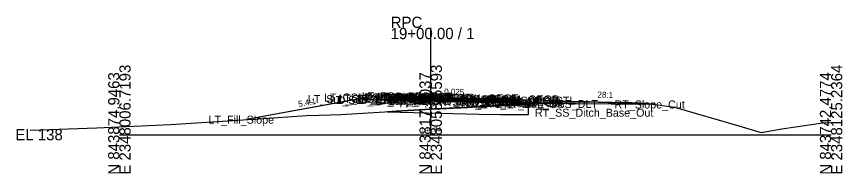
# Model space of a CAD drawing. Extents: x -26 to 203, y -10 to 7538.
# Drawn here: x -3.4 to 202.8, y 5490.3 to 5529.5 of the extents above; entities that cross this region are included whole.
import ezdxf

# ---------------------------------------------------------------- set-up
doc = ezdxf.new("R2010")
doc.units = 0
for name, color, linetype in [('Default', 7, 'Continuous'), ('Exist Cross Section Cell', 7, 'Continuous'), ('Exist XS Center Line Elevation Label', 7, 'Continuous'), ('Exist XS Ground Line', 7, 'Continuous'), ('Prop CMT Pvmt Course 1', 7, 'Continuous'), ('Prop CMT Pvmt Course 2', 7, 'Continuous'), ('Prop CMT Pvmt Course 3', 7, 'Continuous'), ('Prop CMT Pvmt Surface', 7, 'Continuous'), ('Prop CMT Pvmt Surface Shoulder', 7, 'Continuous'), ('Prop CMT Shld Paved Course 1', 7, 'Continuous'), ('Prop CMT Shld Paved Course 2', 7, 'Continuous'), ('Prop CMT Shld Paved Course 3', 7, 'Continuous'), ('Prop CMT Slope Grass', 7, 'Continuous'), ('Prop CMT Subgrade Earthwork', 7, 'Continuous'), ('Prop Road Sect_ Recs - UC (Outline)', 7, 'Continuous'), ('Prop XS Earthwork Shape', 7, 'Continuous'), ('Prop XS SE Text', 7, 'Continuous'), ('Prop XS Side Slope Text', 7, 'Continuous'), ('Scratch_Level_0', 7, 'Continuous')]:
    doc.layers.add(name, color=color, linetype=linetype)

msp = doc.modelspace()

# ---------------------------------------------------------------- linework, layer by layer
at = {"layer": 'Exist Cross Section Cell'}
for p, q in [((100, 5500), (100, 5526.67)), ((22.25, 5500), (100, 5500)), ((100, 5500), (200, 5500))]:
    msp.add_line(p, q, dxfattribs=at)
at = {"layer": 'Exist XS Ground Line'}
msp.add_lwpolyline([(0, 5501.14), (16.64, 5501.73), (35.03, 5502.56), (55.71, 5503.86), (56.28, 5503.9), (57.1, 5503.98), (68.96, 5504.78), (72.1, 5504.89), (77.52, 5505.06), (87.1, 5505.59), (95.79, 5506.1), (100, 5506.34), (102.1, 5506.47), (109.21, 5506.82), (112.93, 5507), (116.65, 5507.23), (123.89, 5507.66), (130.27, 5508.04), (130.72, 5508.03), (131.92, 5508.13), (132.56, 5508.16), (133.8, 5508.19), (135.3, 5508.19), (135.85, 5508.19), (136.47, 5508.19), (138.69, 5508.19), (140.23, 5508.18), (141.17, 5508.17), (142.02, 5508.16), (143.98, 5508.13), (145.36, 5508.11), (147.7, 5508.07), (148.2, 5508.05), (148.66, 5508.05), (150.21, 5508.02), (151.64, 5507.98), (152.22, 5507.94), (153.93, 5507.88), (155.47, 5507.66), (160.91, 5506.9), (176.94, 5502.25), (182.5, 5500.56), (187.68, 5501.44), (197.92, 5503), (200, 5503.05)], dxfattribs=at)
at = {"layer": 'Prop CMT Pvmt Course 1'}
for p, q in [((100, 5509.36), (96, 5509.46)), ((96, 5509.46), (96, 5509.21)), ((96, 5509.21), (100, 5509.11)), ((100, 5509.11), (100, 5509.36)), ((100, 5509.36), (112, 5509.06)), ((100, 5509.11), (100, 5509.36)), ((100, 5509.11), (100, 5509.23)), ((100, 5509.23), (100, 5509.23)), ((100, 5509.23), (100, 5509.11)), ((100, 5509.11), (100, 5509.23)), ((100, 5509.23), (100, 5509.23)), ((100, 5509.23), (100, 5509.11)), ((100, 5509.11), (100, 5509.11)), ((112, 5508.81), (100, 5509.11)), ((100, 5509.11), (100, 5509.11)), ((112, 5509.06), (112, 5508.81))]:
    msp.add_line(p, q, dxfattribs=at)
at = {"layer": 'Prop CMT Pvmt Course 2'}
for p, q in [((100, 5509.11), (96, 5509.21)), ((96, 5509.21), (96, 5508.87)), ((96, 5508.87), (100, 5508.77)), ((100, 5508.77), (100, 5509.11)), ((100, 5508.77), (100, 5509.11)), ((100, 5509.11), (112, 5508.81)), ((112, 5508.47), (100, 5508.77)), ((112, 5508.81), (112, 5508.47))]:
    msp.add_line(p, q, dxfattribs=at)
at = {"layer": 'Prop CMT Pvmt Course 3'}
for p, q in [((100, 5508.77), (96, 5508.87)), ((96, 5508.87), (96, 5508.54)), ((96, 5508.54), (100, 5508.44)), ((100, 5508.44), (100, 5508.77)), ((100, 5508.77), (112, 5508.47)), ((100, 5508.44), (100, 5508.77)), ((112, 5508.14), (100, 5508.44)), ((112, 5508.47), (112, 5508.14))]:
    msp.add_line(p, q, dxfattribs=at)
at = {"layer": 'Prop CMT Pvmt Surface'}
for q in [(96, 5509.46), (112, 5509.06)]:
    msp.add_line((100, 5509.36), q, dxfattribs=at)
at = {"layer": 'Prop CMT Pvmt Surface Shoulder'}
for p, q in [((96, 5509.46), (92, 5509.56)), ((112, 5509.06), (122, 5508.81))]:
    msp.add_line(p, q, dxfattribs=at)
at = {"layer": 'Prop CMT Shld Paved Course 1'}
for p, q in [((92, 5509.56), (91.76, 5509.31)), ((91.76, 5509.31), (96, 5509.21)), ((96, 5509.46), (92, 5509.56)), ((96, 5509.21), (96, 5509.46)), ((112, 5509.06), (122, 5508.81)), ((112, 5508.81), (112, 5509.06)), ((122.26, 5508.55), (112, 5508.81)), ((122, 5508.81), (122.26, 5508.55))]:
    msp.add_line(p, q, dxfattribs=at)
at = {"layer": 'Prop CMT Shld Paved Course 2'}
for p, q in [((91.76, 5509.31), (91.43, 5508.99)), ((91.43, 5508.99), (96, 5508.87)), ((96, 5509.21), (91.76, 5509.31)), ((96, 5508.87), (96, 5509.21)), ((112, 5508.81), (122.26, 5508.55)), ((112, 5508.47), (112, 5508.81)), ((122.6, 5508.21), (112, 5508.47)), ((122.26, 5508.55), (122.6, 5508.21))]:
    msp.add_line(p, q, dxfattribs=at)
at = {"layer": 'Prop CMT Shld Paved Course 3'}
for p, q in [((90.93, 5509), (90.61, 5508.67)), ((90.61, 5508.67), (96, 5508.54)), ((91.43, 5508.99), (90.93, 5509)), ((96, 5508.87), (91.43, 5508.99)), ((96, 5508.54), (96, 5508.87)), ((112, 5508.47), (122.6, 5508.21)), ((112, 5508.14), (112, 5508.47)), ((123.44, 5507.85), (112, 5508.14)), ((122.6, 5508.21), (123.1, 5508.19)), ((123.1, 5508.19), (123.44, 5507.85))]:
    msp.add_line(p, q, dxfattribs=at)
at = {"layer": 'Prop CMT Slope Grass'}
for p, q in [((84, 5509.28), (54, 5503.76)), ((84, 5509.28), (54, 5503.76)), ((92, 5509.56), (84, 5509.28)), ((92, 5509.56), (84, 5509.28)), ((122, 5508.81), (126, 5508.67)), ((126, 5508.67), (155.93, 5507.6))]:
    msp.add_line(p, q, dxfattribs=at)
at = {"layer": 'Prop CMT Subgrade Earthwork'}
for p, q in [((90.61, 5508.67), (81.91, 5508.89)), ((96, 5508.54), (90.61, 5508.67)), ((100, 5508.44), (96, 5508.54)), ((100, 5508.44), (112, 5508.14)), ((112, 5508.14), (123.44, 5507.85)), ((123.44, 5507.85), (155.93, 5507.6))]:
    msp.add_line(p, q, dxfattribs=at)
at = {"layer": 'Prop Road Sect_ Recs - UC (Outline)'}
msp.add_lwpolyline([(117.44, 5505), (124.44, 5505.01), (124.45, 5507.69), (100, 5506.34), (91.45, 5505.84), (89.19, 5505.71), (112, 5505.14)], close=True, dxfattribs=at)
at = {"layer": 'Prop XS Earthwork Shape'}
for points in [[(68.96, 5504.78), (72.1, 5504.89), (77.52, 5505.06), (87.1, 5505.59), (95.79, 5506.1), (100, 5506.34), (102.1, 5506.47), (109.21, 5506.82), (112.93, 5507), (116.65, 5507.23), (123.89, 5507.66), (126.69, 5507.83), (123.44, 5507.85), (112, 5508.14), (100, 5508.44), (96, 5508.54), (90.61, 5508.67), (81.91, 5508.89), (54, 5503.76), (55.71, 5503.86), (56.28, 5503.9), (57.1, 5503.98)], [(126.69, 5507.83), (155.93, 5507.6), (139.56, 5508.18), (138.69, 5508.19), (136.47, 5508.19), (135.85, 5508.19), (135.3, 5508.19), (133.8, 5508.19), (132.56, 5508.16), (131.92, 5508.13), (130.72, 5508.03), (130.27, 5508.04)], [(153.93, 5507.88), (155.47, 5507.66), (155.93, 5507.6), (139.56, 5508.18), (140.23, 5508.18), (141.17, 5508.17), (142.02, 5508.16), (143.98, 5508.13), (145.36, 5508.11), (147.7, 5508.07), (148.2, 5508.05), (148.66, 5508.05), (150.21, 5508.02), (151.64, 5507.98), (152.22, 5507.94)]]:
    msp.add_lwpolyline(points, close=True, dxfattribs=at)

# ---------------------------------------------------------------- texts
at = {"layer": 'Default'}
msp.add_text('-', height=0.0001, dxfattribs=at).set_placement((22.25, 5500))
at = {"layer": 'Exist Cross Section Cell'}
for s, p in [('RPC', (90, 5526.67)), ('19+00.00 / 1', (90, 5523.87)), ('EL 138', (-3.75, 5498.6))]:
    msp.add_text(s, height=2.8, dxfattribs=at).set_placement(p)
for s, p in [('E 2348006.7193', (25.05, 5490)), ('E 2348058.5593', (102.8, 5490)), ('E 2348125.2364', (202.8, 5490)), ('N 843874.9463', (22.25, 5490)), ('N 843817.0037', (100, 5490)), ('N 843742.4774', (200, 5490))]:
    msp.add_text(s, height=2.8, rotation=90, dxfattribs=at).set_placement(p)
at = {"layer": 'Exist XS Center Line Elevation Label'}
msp.add_text('144.34', height=1.2, dxfattribs=at).set_placement((97.55, 5500.74))
at = {"layer": 'Prop XS SE Text'}
msp.add_text('0.025', height=1.5, rotation=358.5679, dxfattribs=at).set_placement((103.34, 5510.02))
at = {"layer": 'Prop XS Side Slope Text'}
for s, rotation, p in [('28:1', 357.9546, (141.63, 5509.29)), ('5.4:1', 10.4261, (67.07, 5506.9))]:
    msp.add_text(s, height=1.5, rotation=rotation, dxfattribs=at).set_placement(p)
at = {"layer": 'Scratch_Level_0'}
for s, p in [('LT_Sub_OSS_DLT', (69.31, 5507.89)), ('LT_GS_OS_CTL', (73.37, 5508.28)), ('LT_Sub_Trench_Out', (74.81, 5507.67)), ('LT_PS3_Shelf_Out', (76.92, 5508)), ('LT_PS3_OEOP', (81.67, 5507.99)), ('LT_PS2_OEOP', (81.99, 5508.31)), ('LT_PS1_OEOP', (82.8, 5508.56)), ('LT_PV2_OEOT', (86.17, 5508.21)), ('LT_PV3_OEOT', (86.17, 5507.87)), ('LT_PV1_OEOT', (86.74, 5508.46)), ('RT_PV2_OEEOP', (89.26, 5508.11)), ('RT_PV3_OEEOP', (89.26, 5507.77)), ('LT_PV2_OEEOP', (89.31, 5508.11)), ('LT_PV3_OEEOP', (89.31, 5507.77)), ('RT_PV1_OEEOP', (89.83, 5508.23)), ('LT_PV1_OEEOP', (89.87, 5508.23)), ('RT_PV2_IEEOP', (89.91, 5508.11)), ('LT_PV2_IEEOP', (89.95, 5508.11)), ('RT_PV1_IEEOP', (90.47, 5508.23)), ('LT_PV1_IEEOP', (90.52, 5508.23)), ('PV2_PGL', (93.91, 5508.11)), ('PV1_PGL', (94.47, 5508.36)), ('RT_PV2_OEOT', (102.13, 5507.81)), ('RT_PV1_OEOT', (102.69, 5508.06)), ('RT_PS1_OEOP', (112.76, 5507.81)), ('LT_Sub_OEOT', (86.08, 5507.54)), ('RT_Sub_OEEOP', (89.17, 5507.44)), ('LT_Sub_OEEOP', (89.21, 5507.44)), ('RT_Sub_OEOT', (102.03, 5507.14)), ('RT_PV3_OEOT', (102.13, 5507.47)), ('RT_Sub_Trench_Out', (107.6, 5506.85)), ('RT_PS3_Shelf_Out', (109.04, 5507.19)), ('RT_PS2_OEOP', (112.45, 5507.55)), ('RT_PS3_OEOP', (112.79, 5507.21)), ('RT_GS_OS_CTL', (115.32, 5507.49)), ('RT_Sub_OSS_DLT', (118.27, 5506.67)), ('RT_Slope_Cut', (145.91, 5506.54)), ('RT_SS_Ditch_Base_Out', (126.03, 5504.49)), ('LT_Fill_Slope', (44.52, 5502.76))]:
    msp.add_text(s, height=2, dxfattribs=at).set_placement(p)

doc.saveas('drawing.dxf')
